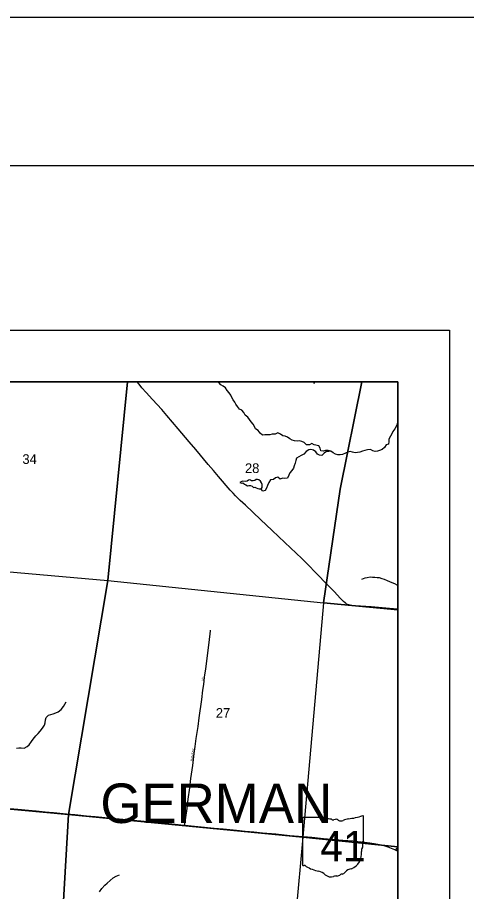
# Model space of a CAD drawing. Extents: x 0 to 680, y 0 to 440.
# Drawn here: x 259.3 to 289.7, y 380.9 to 440 of the extents above; entities that cross this region are included whole.
import ezdxf

# ---------------------------------------------------------------- set-up
doc = ezdxf.new("R2010")
doc.units = 0
for name, color, linetype in [('GM_X_Adjacent_County', 7, 'Continuous'), ('GM_X_County', 7, 'Continuous'), ('GM_X_County_Road', 7, 'Continuous'), ('GM_X_Minor_Lake', 7, 'Continuous'), ('GM_X_Minor_River', 7, 'Continuous'), ('GM_X_Section', 7, 'Continuous'), ('GM_X_Section_Text', 7, 'Continuous'), ('GM_X_State_Location', 7, 'Continuous'), ('GM_X_State_Route', 7, 'Continuous'), ('GM_X_State_Shield', 7, 'Continuous'), ('GM_X_Township', 7, 'Continuous'), ('GM_X_Township_Subdivision', 7, 'Continuous'), ('GM_X_Township_Subdivision_Text', 7, 'Continuous'), ('GM_X_Township_Text', 7, 'Continuous'), ('SH_Border', 7, 'Continuous'), ('SH_Cut_Line', 7, 'Continuous'), ('SH_Data', 7, 'Continuous'), ('SH_Text', 7, 'Continuous')]:
    doc.layers.add(name, color=color, linetype=linetype)

msp = doc.modelspace()

# ---------------------------------------------------------------- linework, layer by layer
at = {"layer": 'GM_X_Adjacent_County'}
msp.add_lwpolyline([(285.035, 209.752), (285.035, 415.359), (154.698, 415.359)], dxfattribs=at)
at = {"layer": 'GM_X_County'}
msp.add_lwpolyline([(285.035, 209.752), (285.035, 415.359), (154.698, 415.359)], dxfattribs=at)
at = {"layer": 'GM_X_County_Road'}
for points in [[(285.035, 399.993), (284.471, 400.038), (283.211, 400.141), (282.144, 400.221), (281.903, 400.243), (281.808, 400.257), (281.716, 400.281), (281.671, 400.297), (281.627, 400.317), (281.544, 400.363), (281.505, 400.389), (281.467, 400.419), (281.36, 400.516), (281.152, 400.72), (280.715, 401.177), (280.175, 401.737), (279.603, 402.334), (278.857, 403.101), (278.546, 403.409), (277.379, 404.51), (276.529, 405.31), (275.755, 406.048), (274.732, 407.018), (274.378, 407.352), (274.064, 407.656), (273.893, 407.828), (273.697, 408.043), (272.906, 408.965), (272.558, 409.372), (272.214, 409.781), (271.367, 410.784), (270.928, 411.304), (270.174, 412.195), (269.423, 413.088), (269.073, 413.493), (268.455, 414.18), (268.027, 414.644), (267.732, 414.967), (267.605, 415.114), (267.516, 415.228), (267.434, 415.347), (267.427, 415.359)], [(284.866, 383.691), (284.892, 383.727), (284.975, 383.836), (285.009, 383.873), (285.035, 383.895)]]:
    msp.add_lwpolyline(points, dxfattribs=at)
at = {"layer": 'GM_X_Minor_Lake'}
for points in [[(275.073, 408.716), (275.032, 408.738), (274.931, 408.711), (274.841, 408.642), (274.752, 408.632), (274.527, 408.638), (274.437, 408.605), (274.347, 408.554), (274.459, 408.515), (274.548, 408.537), (274.658, 408.445), (274.758, 408.401), (274.862, 408.338), (274.957, 408.348), (275.076, 408.345), (275.187, 408.312), (275.262, 408.215), (275.357, 408.242), (275.462, 408.198), (275.562, 408.154), (275.655, 408.122), (275.75, 408.131), (275.785, 408.113)], [(275.785, 408.113), (275.859, 408.212), (275.862, 408.324), (275.858, 408.413), (275.802, 408.528), (275.74, 408.648), (275.636, 408.734), (275.542, 408.754), (275.441, 408.757), (275.35, 408.682), (275.238, 408.661), (275.137, 408.681), (275.073, 408.716)]]:
    msp.add_lwpolyline(points, dxfattribs=at)
at = {"layer": 'GM_X_Minor_River'}
msp.add_line((279.423, 415.359), (279.335, 415.259), dxfattribs=at)
for points in [[(278.034, 411.377), (277.875, 411.411), (277.724, 411.516), (277.573, 411.614), (277.415, 411.684), (277.262, 411.706), (277.099, 411.817), (276.924, 411.922), (276.727, 411.832), (276.543, 411.819), (276.382, 411.782), (276.193, 411.775), (276.027, 411.779), (275.873, 411.748), (275.723, 411.894), (275.579, 412.07), (275.417, 412.193), (275.344, 412.349), (275.254, 412.512), (275.103, 412.652), (274.995, 412.809), (274.881, 412.972), (274.719, 413.113), (274.623, 413.282), (274.485, 413.44), (274.327, 413.515), (274.184, 413.691), (274.087, 413.848), (274.002, 413.998), (273.888, 414.15), (273.797, 414.312), (273.748, 414.474), (273.616, 414.631), (273.502, 414.783), (273.382, 414.952), (273.231, 415.075), (273.068, 415.162), (272.924, 415.32), (272.899, 415.359)], [(285.035, 412.683), (284.994, 412.661), (284.99, 412.501), (284.909, 412.337), (284.822, 412.185), (284.682, 412.01), (284.619, 411.858), (284.526, 411.682), (284.426, 411.495), (284.416, 411.323), (284.388, 411.151), (284.239, 411.108), (284.122, 410.933), (283.97, 410.789), (283.791, 410.716), (283.642, 410.684), (283.482, 410.647), (283.329, 410.704), (283.166, 410.78), (282.982, 410.773), (282.797, 410.712), (282.637, 410.681), (282.457, 410.614), (282.297, 410.589), (282.137, 410.564), (281.966, 410.61), (281.813, 410.649), (281.647, 410.606), (281.479, 410.539), (281.288, 410.455), (281.121, 410.424), (280.962, 410.428), (280.809, 410.48), (280.652, 410.567), (280.501, 410.683), (280.313, 410.73), (280.141, 410.711), (279.986, 410.673), (279.815, 410.701), (279.773, 410.88), (279.694, 411.031), (279.376, 411.099), (279.224, 411.191), (279.051, 411.101), (278.862, 411.112), (278.694, 411.253), (278.53, 411.328), (278.372, 411.38), (278.223, 411.354), (278.034, 411.377)], [(280.512, 410.675), (280.359, 410.663), (280.205, 410.656), (280.054, 410.535), (279.896, 410.391), (279.736, 410.395), (279.585, 410.482), (279.494, 410.633), (279.325, 410.744), (279.155, 410.796), (279, 410.758), (278.838, 410.656), (278.662, 410.482), (278.488, 410.386), (278.338, 410.301), (278.187, 410.192), (278.13, 410.039), (278.084, 409.874), (278.015, 409.686), (277.963, 409.527), (277.858, 409.364), (277.718, 409.201), (277.667, 409.043), (277.561, 408.855), (277.395, 408.83), (277.23, 408.858), (277.075, 408.785), (276.924, 408.908), (276.763, 408.87), (276.613, 408.767), (276.411, 408.731), (276.299, 408.55), (276.212, 408.357), (276.148, 408.18), (276.067, 408.028), (275.912, 407.979), (275.785, 408.113)], [(285.035, 401.593), (284.977, 401.624), (284.814, 401.699), (284.644, 401.781), (284.474, 401.839), (284.316, 401.902), (284.117, 401.997), (283.965, 402.054), (283.777, 402.118), (283.623, 402.104), (283.47, 402.132), (283.311, 402.142), (283.151, 402.146), (282.955, 402.116), (282.789, 402.091), (282.579, 402.007)], [(259.264, 390.595), (259.413, 390.617), (259.579, 390.615), (259.781, 390.588), (259.967, 390.717), (260.117, 390.828), (260.274, 391.046), (260.383, 391.2), (260.558, 391.429), (260.727, 391.576), (260.854, 391.747), (261.005, 391.941), (261.144, 392.141), (261.199, 392.313), (261.22, 392.521), (261.251, 392.675), (261.408, 392.834), (261.569, 392.867), (261.736, 392.907), (261.921, 392.982), (262.071, 393.052), (262.269, 393.216), (262.426, 393.416), (262.517, 393.57), (262.614, 393.735)], [(264.859, 380.878), (265.028, 381.108), (265.215, 381.325), (265.389, 381.466), (265.582, 381.654), (265.798, 381.818), (265.995, 381.94), (266.211, 382.027)]]:
    msp.add_lwpolyline(points, dxfattribs=at)
at = {"layer": 'GM_X_Section'}
for points in [[(266.765, 415.359), (250.747, 415.359), (249.566, 403.328), (265.424, 401.937)], [(282.582, 415.359), (266.765, 415.359), (265.424, 401.937), (280.006, 400.413), (281.119, 408.113)], [(285.035, 399.944), (285.035, 415.359), (282.582, 415.359), (281.119, 408.113), (280.006, 400.413)], [(249.566, 403.328), (265.424, 401.937), (262.767, 386.107), (248.075, 387.46)], [(280.006, 400.413), (278.599, 384.575), (262.767, 386.107), (265.424, 401.937)], [(285.035, 383.915), (285.035, 399.944), (280.006, 400.413), (278.599, 384.575)], [(248.075, 387.46), (262.767, 386.107), (261.88, 370.548), (246.691, 371.915)], [(262.767, 386.107), (278.599, 384.575), (277.185, 369.031), (261.88, 370.548)], [(285.035, 368.251), (285.035, 383.915), (278.599, 384.575), (277.185, 369.031)]]:
    msp.add_lwpolyline(points, close=True, dxfattribs=at)
at = {"layer": 'GM_X_State_Route'}
for points in [[(281.986, 384.296), (281.302, 384.358), (279.995, 384.474), (279.22, 384.546), (277.719, 384.676), (276.79, 384.769), (275.881, 384.859), (275.285, 384.915), (274.711, 384.969), (274.127, 385.026), (273.219, 385.116), (272.622, 385.173), (271.512, 385.281), (270.62, 385.367), (270.558, 385.373), (269.977, 385.43), (269.543, 385.477), (268.903, 385.536), (268.139, 385.608), (267.655, 385.657), (267.123, 385.705), (266.44, 385.77), (265.674, 385.848), (264.561, 385.951), (263.98, 386.005), (263.593, 386.043), (263.206, 386.081), (262.625, 386.136), (261.754, 386.218), (261.19, 386.272), (260.592, 386.326), (260.066, 386.377), (259.343, 386.449), (258.277, 386.544)], [(285.035, 383.607), (284.991, 383.631), (284.866, 383.691), (284.817, 383.715), (284.594, 383.809), (284.367, 383.894), (284.179, 383.958), (283.906, 384.033), (283.672, 384.087), (283.422, 384.136), (283.14, 384.177), (282.802, 384.218), (282.319, 384.265), (281.986, 384.296)]]:
    msp.add_lwpolyline(points, dxfattribs=at)
at = {"layer": 'GM_X_State_Shield'}
for p, q in [((282.703, 384.342), (282.703, 385.98)), ((278.576, 385.849), (278.576, 382.716)), ((279.825, 385.903), (278.616, 385.903)), ((282.703, 384.342), (282.703, 384.342))]:
    msp.add_line(p, q, dxfattribs=at)
for centre, radius, start, end in [((281.233, 390.173), 4.377, 275.84447, 288.90645), ((282.657, 385.987), 0.0459, 351.86209, 97.738), ((278.623, 385.855), 0.0478, 98.1301, 188.1301), ((280.113, 386.266), 0.464, 231.61951, 271.11188), ((280.267, 384.144), 1.665, 80.48669, 94.98827), ((280.645, 385.872), 0.134, 219.79206, 297.10237), ((280.841, 385.509), 0.278, 54.46668, 119.14113), ((281.2, 386.006), 0.335, 233.85621, 294.82819), ((281.791, 384.946), 0.881, 97.34618, 120.76885), ((282.692, 384.221), 0.0711, 107.94398, 210.33697), ((282.24, 384.014), 0.427, 340.03296, 23.64957), ((282.654, 384.335), 0.0492, 289.60381, 7.73413), ((281.478, 383.447), 1.095, 292.30889, 8.98584), ((282.868, 383.656), 0.311, 136.8065, 186.92959), ((278.623, 382.709), 0.0482, 171.95839, 258.30661), ((278.631, 383.03), 0.368, 267.33899, 280.60386), ((278.706, 382.535), 0.133, 29.74838, 93.27175), ((280.382, 385.35), 3.161, 240.41292, 257.1985), ((281.94, 381.837), 0.6, 94.40312, 142.57675), ((279.44, 381.309), 0.989, 47.18416, 75.83597), ((280.509, 382.52), 0.628, 230.70037, 286.29184), ((280.872, 381.437), 0.516, 85.69512, 111.20995), ((280.918, 382.285), 0.334, 268.77702, 315.54927), ((281.22, 381.982), 0.0941, 65.75173, 132.64842), ((281.18, 382.413), 0.354, 282.87319, 323.27711)]:
    msp.add_arc(centre, radius, start, end, dxfattribs=at)
at = {"layer": 'GM_X_Township'}
msp.add_lwpolyline([(285.035, 336.894), (285.035, 415.359), (250.725, 415.359), (249.582, 403.354), (248.114, 387.472), (247.71, 383.022), (247.475, 380.338)], dxfattribs=at)
at = {"layer": 'GM_X_Township_Subdivision'}
msp.add_lwpolyline([(270.62, 385.367), (270.634, 385.465), (270.783, 386.524), (270.866, 387.15), (270.962, 387.921), (271.045, 388.548), (271.162, 389.415), (271.272, 390.234), (271.336, 390.715), (271.408, 391.245), (271.526, 392.063), (271.607, 392.64), (271.772, 393.893), (271.854, 394.52), (271.904, 394.905), (271.967, 395.387), (272.039, 395.966), (272.27, 397.749), (272.366, 398.521), (272.373, 398.569)], dxfattribs=at)
at = {"layer": 'SH_Border'}
msp.add_lwpolyline([(30, 430), (670, 430), (670, 10), (30, 10)], close=True, dxfattribs=at)
at = {"layer": 'SH_Cut_Line'}
msp.add_lwpolyline([(0, 0), (680, 0), (680, 440), (0, 440)], close=True, dxfattribs=at)
at = {"layer": 'SH_Data'}
for p, q in [((43.52, 418.859), (288.52, 418.859)), ((288.52, 418.859), (288.52, 173.859)), ((47.02, 415.359), (285.02, 415.359)), ((285.02, 415.359), (285.02, 177.359))]:
    msp.add_line(p, q, dxfattribs=at)
at = {"layer": 'SH_Text'}
for points in [[(47.02, 415.359), (285.02, 415.359), (285.02, 177.359), (47.02, 177.359)], [(285.019, 415.359), (47.02, 415.359), (47.02, 177.359), (285.019, 177.359)]]:
    msp.add_lwpolyline(points, close=True, dxfattribs=at)

# ---------------------------------------------------------------- texts
at = {"layer": 'GM_X_Section_Text'}
for s, p in [('34', (259.654, 409.813)), ('28', (274.694, 409.2)), ('27', (272.724, 392.647))]:
    msp.add_text(s, height=0.6552, rotation=0.00001, dxfattribs=at).set_placement(p)
at = {"layer": 'GM_X_State_Location'}
msp.add_text('41', height=0.00296, rotation=0.00001, dxfattribs=at).set_placement((279.846, 383.858))
for s in ['s', 'r']:
    msp.add_text(s, height=0.00296, dxfattribs=at).set_placement((280.593, 384.074))
at = {"layer": 'GM_X_State_Shield'}
msp.add_text('41', height=2.0637, dxfattribs=at).set_placement((279.783, 382.937))
at = {"layer": 'GM_X_Township_Subdivision_Text'}
for s, rotation, p in [('LN', 81.03268, (271.901, 395.116)), ('RAMSEY', 82.01112, (271.17, 389.715))]:
    msp.add_text(s, height=0.1482, rotation=rotation, dxfattribs=at).set_placement(p)
at = {"layer": 'GM_X_Township_Text'}
msp.add_text('GERMAN', height=2.6682, rotation=0.00001, dxfattribs=at).set_placement((264.925, 385.536))

doc.saveas('drawing.dxf')
